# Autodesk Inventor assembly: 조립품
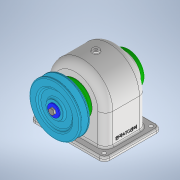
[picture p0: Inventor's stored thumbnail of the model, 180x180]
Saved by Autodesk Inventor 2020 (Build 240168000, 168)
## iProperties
Created: 2022-09
Part Number: 조립품
Document SubType Name: Assembly
Designer: Administrator
Author: Administrator
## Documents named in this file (16)
- C:\Users\Administrator\Desktop\720906V1013\조립품.iam
- C:\Users\Administrator\Desktop\720906V1013\본체.ipt
- C:\Users\Administrator\Desktop\720906V1013\축.ipt
- C:\Users\Administrator\Desktop\720906V1013\앞커버.ipt
- C:\Users\Administrator\Desktop\720906V1013\뒤커버.ipt
- C:\Users\Administrator\Desktop\720906V1013\베어링 6203.ipt
- C:\Users\Administrator\Desktop\720906V1013\스퍼기어.ipt
- C:\Users\Administrator\Desktop\720906V1013\오일 실 17 x 30 x 8.ipt
- C:\Users\Administrator\Desktop\720906V1013\칼라.ipt
- C:\Users\Administrator\Desktop\720906V1013\키 5 x 5 x 18.ipt
- C:\Users\Administrator\Desktop\720906V1013\키 6 x 6 x 22.ipt
- C:\Users\Administrator\Desktop\720906V1013\V-벨트풀리.ipt
- C:\Users\Administrator\Desktop\720906V1013\와셔 6 x 22.ipt
- C:\Users\Administrator\Desktop\720906V1013\육각머리볼트 M3 x 8.ipt
- C:\Users\Administrator\Desktop\720906V1013\볼트 M3 x 10.ipt
- C:\Users\Administrator\Desktop\720906V1013\멈춤나사 M4 x 10.ipt
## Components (9 placed, 2 different names)
1. V-벨트풀리:1 — 플러쉬:1
2. ISO 4762 M3 x 10:1
3. ISO 4762 M3 x 10:2
4. ISO 4762 M3 x 10:3
5. ISO 4762 M3 x 10:4
6. ISO 4762 M3 x 10:5
7. ISO 4762 M3 x 10:6
8. ISO 4762 M3 x 10:7
9. ISO 4762 M3 x 10:8
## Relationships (1: Flush 1)
- 플러쉬:1 [Flush]: V-벨트풀리:1
